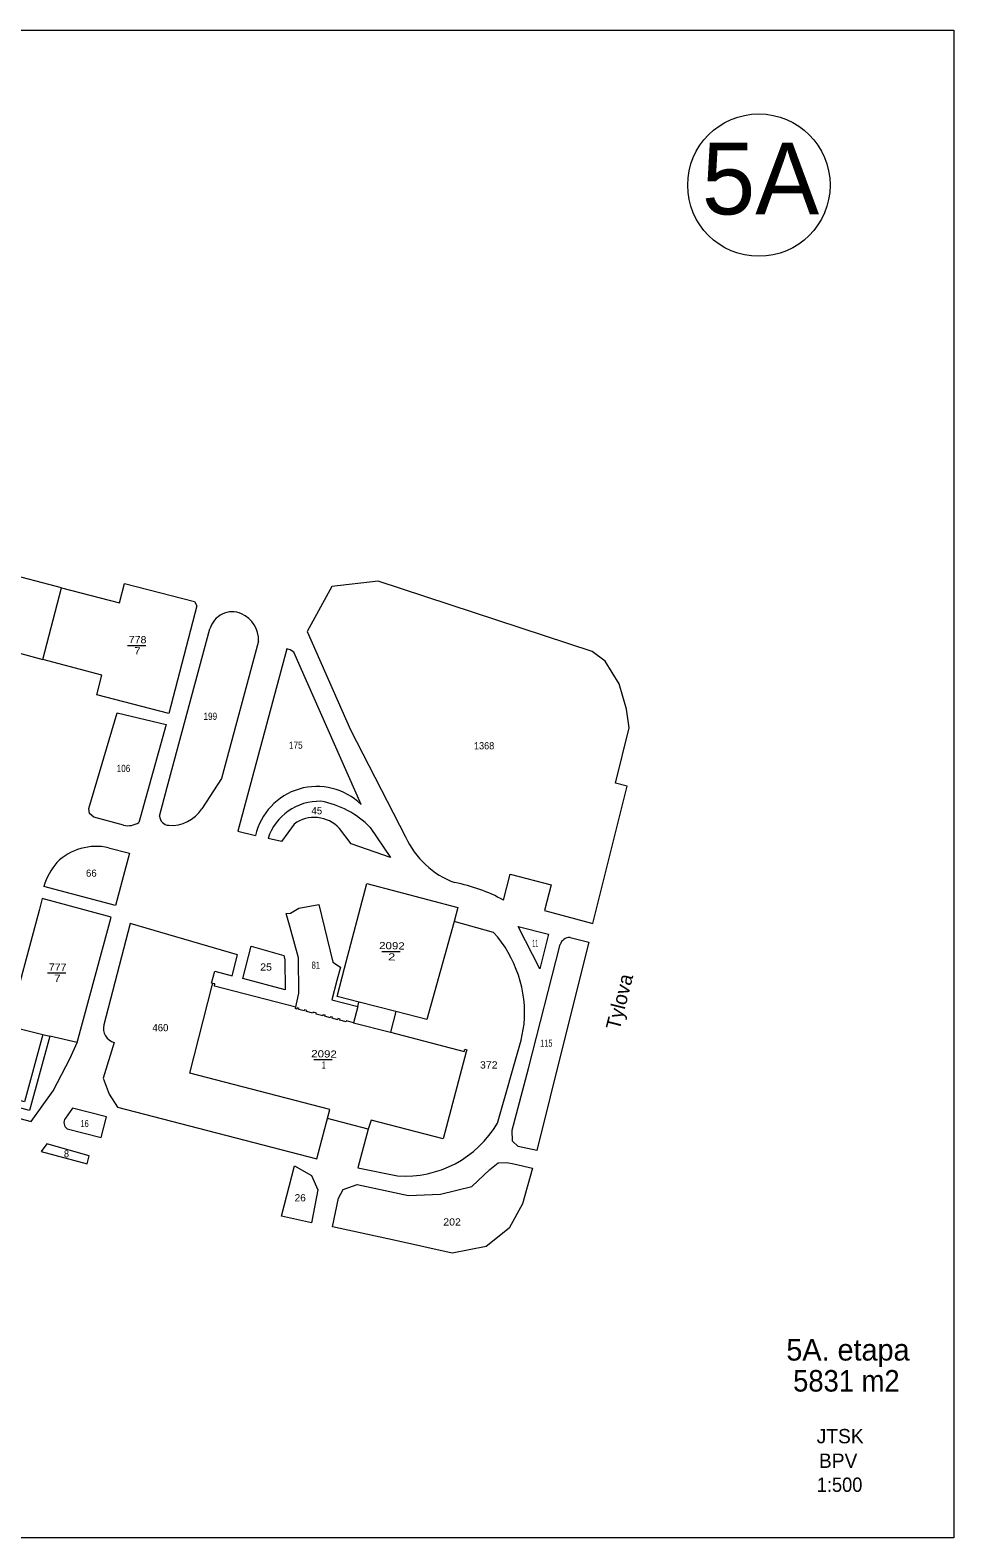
# Model space of a CAD drawing. Extents: x -843443 to -843145, y -1003566 to -1003356.
# Drawn here: x -843273.6 to -843144.9, y -1003566.1 to -1003356.1 of the extents above; entities that cross this region are included whole.
import ezdxf
from ezdxf.enums import TextEntityAlignment as Align

# ---------------------------------------------------------------- set-up
doc = ezdxf.new("R2010")
doc.units = 0
doc.header["$LTSCALE"] = 0.4
doc.layers.add('20', color=7, linetype='Continuous')
for name, color, linetype, lineweight in [('35', 7, 'Continuous', 13), ('38', 7, 'Continuous', 13), ('43', 7, 'Continuous', 13), ('44', 7, 'Continuous', 13)]:
    doc.layers.add(name, color=color, linetype=linetype, lineweight=lineweight)

msp = doc.modelspace()

# ---------------------------------------------------------------- linework, layer by layer
at = {"layer": '35'}
for p, q in [((-843260.085, -1003441.812), (-843257.525, -1003441.812)), ((-843224.649, -1003484.447), (-843222.089, -1003484.447)), ((-843271.235, -1003487.431), (-843268.675, -1003487.431)), ((-843234.11, -1003499.51), (-843231.55, -1003499.51))]:
    msp.add_line(p, q, dxfattribs=at)
at = {"layer": '38'}
for p, q in [((-843227.977, -1003492.118), (-843227.819, -1003491.498)), ((-843222.66, -1003492.81), (-843227.814, -1003491.499)), ((-843228.57, -1003494.38), (-843223.43, -1003495.68)), ((-843271.88, -1003496), (-843270.908, -1003496.234)), ((-843226.55, -1003509.2), (-843232.212, -1003507.729))]:
    msp.add_line(p, q, dxfattribs=at)
for points in [[(-843269.27, -1003433.78), (-843277.38, -1003431.66), (-843276.69, -1003428.99), (-843286.35, -1003426.45), (-843287.02, -1003426.78), (-843290.46, -1003440.54), (-843298.24, -1003438.52), (-843300.14, -1003445.64), (-843282.35, -1003450.26), (-843280.09, -1003441.55), (-843271.86, -1003443.76)], [(-843227.814, -1003491.499), (-843230.851, -1003490.703), (-843229.821, -1003486.774), (-843226.733, -1003475.001), (-843214.034, -1003478.337), (-843214.569, -1003480.264)], [(-843267.1, -1003497.15), (-843262.83, -1003481.4), (-843262.362, -1003479.672), (-843271.96, -1003477.07), (-843272.36, -1003478.76), (-843276.71, -1003494.83)], [(-843236.63, -1003492.222), (-843247.97, -1003489.26), (-843247.89, -1003488.97), (-843248.18, -1003488.89)]]:
    msp.add_lwpolyline(points, dxfattribs=at)
for points in [[(-843250.76, -1003435.71), (-843250.4, -1003436.29), (-843254.3, -1003451.3), (-843264.35, -1003448.7), (-843263.64, -1003445.96), (-843271.86, -1003443.76), (-843269.27, -1003433.78), (-843261.19, -1003435.89), (-843260.48, -1003433.19)], [(-843300, -1003498.41), (-843298.61, -1003493.41), (-843298.07, -1003491.44), (-843297.556, -1003489.565), (-843295.27, -1003490.11), (-843276.71, -1003494.83), (-843271.88, -1003496), (-843274.44, -1003505.383)]]:
    msp.add_lwpolyline(points, close=True, dxfattribs=at)
at = {"layer": '43'}
for p, q in [((-843241.81, -1003441.22), (-843246.97, -1003460.37)), ((-843246.97, -1003460.37), (-843249.72, -1003464.59)), ((-843244.72, -1003467.7), (-843242.242, -1003468.299)), ((-843261.735, -1003478.059), (-843271.74, -1003475.39)), ((-843267.718, -1003506.259), (-843268.73, -1003507.659))]:
    msp.add_line(p, q, dxfattribs=at)
for points in [[(-843201.982, -1003478.759), (-843195.212, -1003480.537), (-843190.438, -1003461.422), (-843192.088, -1003461.01), (-843190.162, -1003453.297), (-843190.549, -1003450.686), (-843191.559, -1003447.171), (-843193.534, -1003444.036), (-843195.348, -1003442.683), (-843225.14, -1003432.86), (-843231.623, -1003433.607), (-843235.04, -1003439.86), (-843228.98, -1003453.59), (-843221.345, -1003468.483)], [(-843255.627, -1003465.607), (-843254.54, -1003461.58), (-843248.58, -1003439.51)], [(-843227.523, -1003463.971), (-843236.885, -1003442.757), (-843237.395, -1003442.444), (-843237.866, -1003442.28), (-843244.72, -1003467.7)], [(-843260.65, -1003466.88), (-843264.77, -1003465.73), (-843265.35, -1003465.22), (-843265.44, -1003464.54), (-843261.498, -1003451.191)], [(-843261.498, -1003451.191), (-843254.679, -1003452.854), (-843258.32, -1003465.85), (-843258.5, -1003466.48)], [(-843236.868, -1003466.712), (-843238.609, -1003469.141), (-843240.492, -1003468.708)], [(-843226.259, -1003467.173), (-843223.426, -1003471.345), (-843228.899, -1003469.458), (-843230.523, -1003467.331)], [(-843262.7, -1003470), (-843259.792, -1003470.776), (-843261.735, -1003478.059)], [(-843207.695, -1003477.285), (-843206.748, -1003473.681), (-843201.042, -1003475.18), (-843201.982, -1003478.759)], [(-843231.88, -1003506.45), (-843251.37, -1003501.39), (-843248.26, -1003489.18), (-843248.18, -1003488.89), (-843248.346, -1003488.847), (-843247.915, -1003487.203), (-843245.51, -1003487.833), (-843244.75, -1003484.936), (-843259.685, -1003480.568), (-843263.35, -1003494.67)], [(-843209.055, -1003481.795), (-843214.569, -1003480.264), (-843218.36, -1003493.92)], [(-843198.4, -1003482.52), (-843195.806, -1003483.158), (-843199.31, -1003497.241), (-843203.03, -1003512.19)], [(-843203.03, -1003512.19), (-843205.62, -1003511.6), (-843206.42, -1003510.88), (-843206.48, -1003509.32), (-843204.19, -1003500.77), (-843199.77, -1003483.5)], [(-843218.36, -1003493.92), (-843222.66, -1003492.81), (-843223.43, -1003495.68), (-843213.17, -1003498.36), (-843213.09, -1003498.07), (-843212.8, -1003498.15), (-843212.88, -1003498.44), (-843216.1, -1003510.55), (-843226.14, -1003507.94), (-843226.55, -1003509.2), (-843227.98, -1003514.573), (-843222.43, -1003515.71)], [(-843208.53, -1003508.35), (-843205.22, -1003496.79), (-843204.792, -1003494.585)], [(-843261.93, -1003497.14), (-843263.47, -1003502.08), (-843262.65, -1003504.33), (-843261.481, -1003506.113), (-843233.67, -1003513.339), (-843231.88, -1003506.45)], [(-843268.478, -1003509.172), (-843263.724, -1003510.365), (-843262.986, -1003507.489), (-843267.718, -1003506.259)], [(-843268.478, -1003509.172), (-843263.724, -1003510.365), (-843262.986, -1003507.489)]]:
    msp.add_lwpolyline(points, dxfattribs=at)
for points in [[(-843237.95, -1003479.14), (-843237.34, -1003479.11), (-843236.21, -1003478.42), (-843233.39, -1003477.91), (-843231.44, -1003485.96), (-843230.41, -1003486.62), (-843230.895, -1003488.471), (-843231.603, -1003491.167), (-843227.977, -1003492.118), (-843228.57, -1003494.38), (-843229.569, -1003494.118), (-843229.607, -1003494.263), (-843230.5, -1003494.029), (-843230.462, -1003493.884), (-843230.753, -1003493.808), (-843230.791, -1003493.953), (-843231.539, -1003493.756), (-843231.501, -1003493.611), (-843231.791, -1003493.535), (-843231.829, -1003493.68), (-843232.58, -1003493.483), (-843232.542, -1003493.338), (-843232.832, -1003493.262), (-843232.87, -1003493.407), (-843233.766, -1003493.172), (-843233.728, -1003493.027), (-843234.212, -1003492.9), (-843234.25, -1003493.045), (-843235.143, -1003492.811), (-843235.105, -1003492.666), (-843235.396, -1003492.59), (-843235.434, -1003492.735), (-843236.182, -1003492.539), (-843236.144, -1003492.394), (-843236.434, -1003492.318), (-843236.472, -1003492.463), (-843236.672, -1003492.41), (-843236.197, -1003490.275), (-843236.252, -1003485.334), (-843237.406, -1003481.118)], [(-843205.644, -1003480.986), (-843201.39, -1003482.04), (-843202.63, -1003486.87)], [(-843242.824, -1003483.69), (-843238.31, -1003485.015), (-843238.15, -1003485.6), (-843238.104, -1003489.775), (-843244.013, -1003488.226)], [(-843273.731, -1003506.584), (-843300.026, -1003499.41), (-843300.07, -1003501.07), (-843273.496, -1003508.115), (-843270.42, -1003503.86), (-843268.08, -1003499.33), (-843267.1, -1003497.15), (-843270.908, -1003496.234)], [(-843271.314, -1003511.232), (-843272.1, -1003512.32), (-843265.685, -1003514.008), (-843265.436, -1003512.918)], [(-843238.61, -1003521.33), (-843236.81, -1003514.29), (-843234.43, -1003515.64), (-843233.53, -1003517.65), (-843234.42, -1003522.26)], [(-843231.53, -1003522.79), (-843230.68, -1003518.81), (-843230.04, -1003517.61), (-843228.06, -1003516.91), (-843220.94, -1003518.45), (-843216.47, -1003518.26), (-843212.1, -1003517.19), (-843209.6, -1003514.84), (-843208.42, -1003513.9), (-843207.21, -1003513.82), (-843206.227, -1003514.049), (-843203.64, -1003514.65), (-843205.03, -1003519.58), (-843206.9, -1003522.98), (-843210.1, -1003525.56), (-843214.83, -1003526.45), (-843222.75, -1003524.69)]]:
    msp.add_lwpolyline(points, close=True, dxfattribs=at)
for centre, radius, start, end in [((-843245.4826, -1003440.3465), 3.2084, 66.2414, 164.88776), ((-843245.7979, -1003441.0628), 3.991, 357.74232, 66.2414), ((-843233.6673, -1003470.2668), 8.7976, 45.69757, 167.07357), ((-843233.3479, -1003471.0483), 7.5177, 88.34125, 161.8632), ((-843235.2791, -1003475.8989), 12.5504, 44.05085, 80.14149), ((-843254.2302, -1003465.4806), 1.4029, 185.16424, 265.92206), ((-843253.9693, -1003461.8209), 5.072, 265.92206, 326.90937), ((-843234.0388, -1003470.5406), 4.7604, 42.38902, 126.45997), ((-843260.087, -1003463.9242), 3.009, 259.21674, 301.83782), ((-843264.4158, -1003477.6971), 7.886, 77.43345, 134.16325), ((-843210.1773, -1003463.3457), 12.2925, 204.70422, 249.52642), ((-843261.87, -1003478.6069), 10.381, 140.75911, 161.94809), ((-843218.678, -1003497.3243), 22.852, 61.27431, 79.40652), ((-843221.7172, -1003493.1213), 16.9886, 355.05588, 41.81237), ((-843198.5024, -1003483.8244), 1.3084, 85.51029, 165.64415), ((-843261.3816, -1003495.1815), 2.0338, 165.43248, 254.35661), ((-843267.8566, -1003508.2909), 1.0783, 144.13519, 234.83129), ((-843221.3914, -1003500.8657), 14.8806, 265.99793, 329.80419)]:
    msp.add_arc(centre, radius, start, end, dxfattribs=at)
at = {"layer": '44'}
msp.add_lwpolyline([(-843442.925, -1003356.123), (-843144.925, -1003356.123), (-843144.925, -1003566.123), (-843442.925, -1003566.123)], close=True, dxfattribs=at)
msp.add_circle((-843172.0927, -1003377.7069), 9.9163, dxfattribs=at)

# ---------------------------------------------------------------- texts
at = {"layer": '20'}
msp.add_text('Tylova', height=2, rotation=75.94, dxfattribs=at).set_placement((-843191.508, -1003495.511))
at = {"layer": '35'}
for s, width, p in [('778', 1.1, (-843258.6745, -1003441.5145)), ('7', 1.2, (-843258.708, -1003443.0649)), ('2092', 1.2, (-843223.237, -1003484.1495)), ('2', 1.35, (-843223.272, -1003485.6993)), ('777', 1.1, (-843269.8235, -1003487.1337)), ('7', 1.2, (-843269.858, -1003488.6839)), ('2092', 1.2, (-843232.699, -1003499.2135)), ('1', 0.7, (-843232.7345, -1003500.7628))]:
    msp.add_text(s, height=1, rotation=358.734, dxfattribs=dict(at, width=width)).set_placement(p, align=Align.CENTER)
at = {"layer": '43'}
for s, width, p in [('199', 0.85, (-843249.482, -1003452.191)), ('175', 0.85, (-843237.568, -1003456.215)), ('1368', 0.95, (-843211.797, -1003456.295)), ('106', 0.85, (-843261.584, -1003459.446)), ('11', 0.45, (-843203.672, -1003483.8)), ('25', 1.1, (-843241.584, -1003487.114)), ('81', 0.75, (-843234.406, -1003486.858)), ('115', 0.7, (-843202.559, -1003497.722)), ('372', 1.1, (-843210.958, -1003500.752)), ('16', 0.7, (-843266.608, -1003508.916)), ('8', 0.95, (-843268.933, -1003513.13)), ('26', 1.05, (-843236.788, -1003519.255)), ('202', 1.1, (-843216.076, -1003522.622))]:
    msp.add_text(s, height=1, dxfattribs=dict(at, width=width)).set_placement(p)
for s, p in [('45', (-843234.437, -1003465.334)), ('66', (-843265.857, -1003474.039)), ('460', (-843256.605, -1003495.558))]:
    msp.add_text(s, height=1, dxfattribs=at).set_placement(p)
at = {"layer": '44'}
for s, height, p in [('5A', 10, (-843180.045, -1003381.788)), ('5A. etapa', 3, (-843168.27, -1003541.431)), ('JTSK', 2, (-843164.034, -1003552.956)), ('BPV', 2, (-843163.723, -1003556.384))]:
    msp.add_text(s, height=height, dxfattribs=at).set_placement(p)
at = {"layer": '44', "width": 0.95}
for s, height, p in [('5831 m2', 3, (-843167.319, -1003545.75)), ('1:500', 2, (-843164.03, -1003559.719))]:
    msp.add_text(s, height=height, dxfattribs=at).set_placement(p)

doc.saveas('drawing.dxf')
